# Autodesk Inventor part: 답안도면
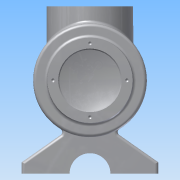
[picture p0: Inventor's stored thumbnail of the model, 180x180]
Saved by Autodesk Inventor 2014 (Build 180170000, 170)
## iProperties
Created: 2017-04
Part Number: 답안도면
Material: 알루미늄 6061
Document SubType Name: Modeling
Designer: NET
Mass: 1666.1 g
Surface Area: 1068.54 cm^2
Volume: 614.797 cm^3
Density: 2.71 g/cm^3
Appearance: 알루미늄 - 평지
Author: NET
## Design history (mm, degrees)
sketch "스케치1"
  geometry: L1 (-60, -40)-(60, -40); L2 (60, -40)-(60, 40); L3 (60, 40)-(-60, 40); L4 (-60, 40)-(-60, -40); L5 (-60, -40)-(60, 40); L6 (60, -40)-(-60, 40); 1 further point
  constraints: 12 end point, 2 midpoint, 2 parallel, 1 horizontal, 1 perpendicular
  dimensions: "d0" = 120 distance of L3.end L2.end; "d1" = 80 distance of L2.end L1.end
extrude "돌출1" new body sketch "스케치1" distance "d2" = 10; taper "d3" = 0 deg
sketch "스케치2"
  geometry: L1 (60, 0)-(-60, 0) reference; L2 (-60, 0)-(-60, 10) reference; L3 (60, 10)-(-60, 10) reference; L4 (60, 0)-(60, 10) reference; L5 (-60, 10)-(0, 52.012); L6 (-60, 10)-(13.246, 10); L7 (0, 52.012)-(60, 10); 1 further point
  constraints: 6 end point, 1 equal length, 1 horizontal
  dimensions: "d4" = 35 deg angle of L6 L5; "d5" = 35 deg angle of L1 L7
extrude "돌출2" join sketch "스케치2" stored distance "d6" = 80; taper "d7" = 0 deg
sketch "스케치3"
  geometry: C1 r 50 at (0, 82); 1 further point
  constraints: 1 centre point, 1 vertical alignment
  dimensions: "d8" = 100 diameter of C1; "d9" = 82 distance of point (0, 0) C1.centre
extrude "돌출3" join sketch "스케치3" stored distance "d10" = 108; taper "d11" = 0 deg
sketch "스케치4"
  geometry: C1 r 50 at (0, 0) reference; C2 r 37.5 at (0, 0); 1 further point
  constraints: 1 centre point, 1 coincident
  dimensions: "d12" = 75 diameter of C2
extrude "돌출4" join sketch "스케치4" distance "d13" = 12; taper "d14" = 0 deg
sketch "스케치5"
  geometry: L1 (119.5, 66)-(44.5, 66) reference; L2 (32, -54)-(132, -54) reference; L3 (82, 66)-(82, 59); L4 (82, 59)-(82, -54); L5 (82, 59)-(195, 59); L6 (132, -42.336)-(82, -42.336); L7 (82, -54)-(82, -42.336); L8 (132, -42.336)-(132, -54); L9 (82, -54)-(82, -42.336); L10 (132, -54)-(82, -54); 1 further point
  constraints: 16 end point, 4 perpendicular, 2 midpoint, 1 coincident, 1 collinear, 1 horizontal, 1 parallel, 1 point on line
  dimensions: "d18" = 7 distance of L3.start L3.end; "d19" = 90 deg angle of L4 L5; "d20" = 11.66393 distance from line of L2.end L6
revolve "회전1" sketch "스케치5" stored, may be unused: angle "d21" = 90 deg
sketch "스케치6"
  geometry: L1 (119.5, 66)-(44.5, 66) reference; L2 (82, 66)-(82, 59); L3 (82, 59)-(82, -54); L4 (82, 59)-(195, 59); L5 (132, -42.336)-(32, -42.336) reference; L6 (132, -42.336)-(82, -42.336); L7 (82, -54)-(82, -42.336); A1 r 113 centre (82, 59) between (82, -54) and (132, -42.336); 1 further point
  constraints: 10 end point, 2 midpoint, 2 perpendicular, 2 point on circle, 1 centre point, 1 coincident, 1 horizontal, 1 point on line
  dimensions: "d22" = 7 distance of L2.start L2.end; "d23" = 113 radius of A1; "d24" = 90 deg angle of L3 L4
revolve "회전2" sketch "스케치6" stored, may be unused: angle "d25" = 90 deg
sketch "스케치7"
  geometry: C1 r 37.5 at (0, 0) reference; C2 r 27 at (0, 0); 1 further point
  constraints: 1 centre point, 1 coincident
  dimensions: "d26" = 54 diameter of C2
extrude "돌출5" cut sketch "스케치7" distance "d27" = 22; taper "d28" = 0 deg
sketch "스케치8"
  geometry: L1 (55, 44)-(109, 44) reference; L2 (132, -42.336)-(132, 54) reference; L3 (82, 44)-(82, -44); L4 (82, 44)-(122, 44); L5 (122, 44)-(122, -35.916); A1 r 113 centre (82, 59) between (32, -42.336) and (132, -42.336) reference; A2 r 103 centre (82, 59) between (82, -44) and (122, -35.916); 1 further point
  constraints: 6 end point, 2 perpendicular, 2 point on circle, 1 centre point, 1 midpoint, 1 parallel
  dimensions: "d29" = 10 radial gap between concentric circles of A1 A2; "d30" = 40 distance of L3.start L4.end
revolve "회전3" sketch "스케치8" stored, may be unused: angle "d31" = 90 deg
node "작업 평면1"
sketch "스케치13"
  geometry: L1 (50, 54)-(-50, 54) reference; C1 r 38 at (0, 4); 1 further point
  constraints: 1 centre point
  dimensions: "d44" = 76 diameter of C1; "d45" = 50 distance from line of C1.centre L1; "d46" = 70.71068 distance of L1.start C1.centre
extrude "돌출8" join sketch "스케치13" stored distance "d47" = 40; taper "d48" = 0 deg
sketch "스케치14"
  geometry: C1 r 38 at (0, 0) reference; C2 r 27 at (0, 0); 1 further point
  constraints: 1 centre point, 1 coincident
  dimensions: "d49" = 54 diameter of C2
extrude "돌출9" cut sketch "스케치14" distance "d50" = 40; taper "d51" = 0 deg
sketch "스케치15"
  geometry: C1 r 18 at (60, 0); 1 further point
  constraints: 1 centre point, 1 coincident
  dimensions: "d52" = 36 diameter of C1
extrude "돌출10" cut sketch "스케치15" stored distance "d53" = 40; taper "d54" = 0 deg
sketch "스케치18"
  geometry: L1 (60, 40)-(60, -40) reference; L2 (18, 40)-(60, 40) reference; L3 (60, 40)-(60, 20); L4 (60, 20)-(50, 20); L5 (50, 20)-(50, 40); L6 (60, 40)-(50, 40); C1 r 4 at (50, 20); 1 further point
  constraints: 8 end point, 2 perpendicular, 2 point on line, 1 centre point, 1 coincident, 1 collinear
  dimensions: "d69" = 20 distance of L1.start L3.end; "d70" = 10 distance of L3.end L4.end; "d71" = 8 diameter of C1
extrude "돌출12" cut sketch "스케치18" distance "d72" = 6; taper "d73" = 0 deg
sketch "스케치21"
  geometry: L1 (10, 20)-(10, -60) reference; L2 (0, 8)-(10, 8); L3 (10, -8)-(0, -8); L4 (10, 8)-(10, -8); C1 r 4 at (0, 0) reference; A1 r 8 centre (0, 0) between (0, 8) and (0, -8); 1 further point
  constraints: 6 end point, 2 perpendicular, 2 point on circle, 2 point on line, 2 tangent, 1 centre point, 1 coincident
  dimensions: "d76" = 16 diameter of A1
extrude "돌출13" cut sketch "스케치21" distance "d77" = 20; taper "d78" = 0 deg
sketch "스케치22" dims "d79" = 65
  geometry: C1 r 37.5 at (0, 0) reference; 3 further points
  constraints: 1 coincident, 1 horizontal alignment, 2 other
  dimensions: "d80" = 88.20573 distance of point (0, -82) point (-32.5, 0)
hole "구멍2" sketch "스케치22" at (-32.5, 0) diameter "d81" = 3.459; stored, may be unused: countersink angle "d85" = 90 deg, drill point angle "d87" = 118 deg; dims "d82" = 8, "d83" = 4, "d84" = 2, "d86" = 10
sketch "스케치23" dims "d91" = 65
  geometry: C1 r 38 at (0, 0) reference; 3 further points
  constraints: 1 coincident, 1 horizontal alignment, 2 other
  dimensions: "d92" = 32.74523 distance of point (0, 4) point (-32.5, 0)
hole "구멍3" sketch "스케치23" at (-32.5, 0) diameter "d93" = 3.459; stored, may be unused: countersink angle "d97" = 90 deg, drill point angle "d99" = 118 deg; dims "d94" = 8, "d95" = 4, "d96" = 2, "d98" = 10
fillet "모깎기1" dims "d103" = 3
fillet "모깎기2" dims "d104" = 3
chamfer "모따기1" distance "d105" = 1; stored, may be unused: second distance "d106" = 2, angle "d107" = 45 deg
node "작업 평면3"
sketch "스케치24"
  geometry: 3 further points
  constraints: 2 coincident, 1 other
feature "엠보싱1" sketch "스케치24" dims "d0" = 120, "d1" = 80, "d109" = 0.5, "d110" = 0
node "솔리드1"
mirror "대칭1"
mirror "대칭2"
pattern_circular "원형 패턴1" dims angle "d89" = 360 deg
pattern_circular "원형 패턴2" dims angle "d101" = 360 deg
node "투영된 루프1"
other parameters: "d32" = 147
